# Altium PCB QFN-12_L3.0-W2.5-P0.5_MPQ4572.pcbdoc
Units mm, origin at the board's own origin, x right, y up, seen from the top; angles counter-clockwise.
Board outline 15.91 x 16.3 mm, 2 copper layers (Top Layer, Bottom Layer), stack 0 mm thick; 1 components, 0 nets, 12 pads, 0 vias.
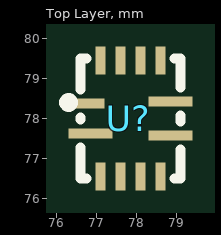
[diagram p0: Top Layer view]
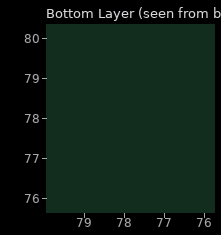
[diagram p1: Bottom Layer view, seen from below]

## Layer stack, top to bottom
Top Layer: signal copper (thickness not stored)
Bottom Layer: signal copper (thickness not stored)

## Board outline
85.758,69.85 69.85,69.85 69.85,86.15 85.758,86.15

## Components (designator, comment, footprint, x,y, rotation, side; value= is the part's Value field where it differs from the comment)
U? "" QFN-12_L3.0-W2.5-P0.5_MPQ4572 77.808,78 r0 top

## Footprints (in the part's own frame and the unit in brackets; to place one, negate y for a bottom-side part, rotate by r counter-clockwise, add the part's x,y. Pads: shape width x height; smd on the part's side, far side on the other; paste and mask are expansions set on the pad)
QFN-12_L3.0-W2.5-P0.5_MPQ4572 [mm]
  rect 0.9x0.25 smd: 1(-1.05,0.375)
  rect 1.1x0.25 smd: 2(-0.95,-0.375) 7(1.05,-0.425) 8(1.05,0.425)
  rect 0.25x0.7 smd: 3(-0.7,-1.45) 4(-0.2,-1.45) 5(0.3,-1.45) 6(0.8,-1.45) 9(0.8,1.45) 10(0.3,1.45) 11(-0.2,1.45) 12(-0.7,1.45)
  silkscreen extent -1.61,-1.5 1.3,1.5

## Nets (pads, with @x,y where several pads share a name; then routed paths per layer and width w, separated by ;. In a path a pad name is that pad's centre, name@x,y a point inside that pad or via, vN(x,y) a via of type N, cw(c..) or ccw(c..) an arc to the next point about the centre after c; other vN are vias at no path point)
pads on no net: U?.1 U?.2 U?.3 U?.4 U?.5 U?.6 U?.7 U?.8 U?.9 U?.10 U?.11 U?.12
